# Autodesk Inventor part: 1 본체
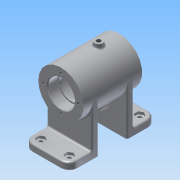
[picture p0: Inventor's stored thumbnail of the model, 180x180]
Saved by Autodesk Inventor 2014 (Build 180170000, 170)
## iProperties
Created: 2017-02
Part Number: 1 본체
Material: 알루미늄 6061
Document SubType Name: Modeling
Designer: 601-
Density: 2.71 g/cm^3
Appearance: 알루미늄 - 평지
Mass: 354.752 g
Surface Area: 426.244 cm^2
Volume: 130.905 cm^3
Author: 601-
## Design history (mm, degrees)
sketch "스케치1"
  geometry: L1 (-27, 52)-(27, 52); L2 (27, 52)-(27, -52); L3 (27, -52)-(-27, -52); L4 (-27, -52)-(-27, 52); L5 (-27, 52)-(27, -52); L6 (27, 52)-(-27, -52); L7 (-27, 17)-(27, 17); L8 (27, 17)-(27, -17); L9 (27, -17)-(-27, -17); L10 (-27, -17)-(-27, 17); L11 (-27, 17)-(27, -17); L12 (27, 17)-(-27, -17); 1 further point
  constraints: 24 end point, 4 midpoint, 4 parallel, 2 horizontal, 2 perpendicular, 1 point on line
  dimensions: "d0" = 54 distance of L1.start L1.end; "d1" = 104 distance of L1.end L2.end; "d2" = 17 distance from line of point (0, 0) L7
extrude "돌출1" new body sketch "스케치1" distance "d3" = 8; taper "d4" = 0 deg
sketch "스케치2"
  geometry: L1 (27, 0)-(-27, 0) reference; C1 r 27 at (0, 60); 1 further point
  constraints: 1 centre point, 1 vertical alignment
  dimensions: "d5" = 60 distance from line of C1.centre L1; "d6" = 54 diameter of C1
extrude "돌출2" join sketch "스케치2" stored distance "d7" = 70; taper "d8" = 0 deg
sketch "스케치3"
  geometry: L1 (27, -52)-(27, -17) reference; L2 (-27, -17)-(27, -17); L3 (27, -17)-(27, -25); L4 (27, -25)-(-27, -25); L5 (-27, -25)-(-27, -17); 1 further point
  constraints: 8 end point, 2 parallel, 1 horizontal, 1 perpendicular, 1 point on line
  dimensions: "d9" = 8 distance between parallel lines of L4 L2
extrude "돌출3" join sketch "스케치3" stored distance "d10" = 70; taper "d11" = 0 deg
node "작업 평면1"
node "작업 평면7"
sketch "스케치6"
  geometry: L1 (-35, 87)-(-35, 33) reference; L2 (-35, 87)-(35, 87) reference; L3 (-35, 60)-(-23, 60); L4 (-23, 60)-(-23, 76); L5 (-23, 76)-(-35, 76); L6 (-35, 76)-(-35, 60); L7 (-23, 60)-(-20, 60); L8 (-20, 60)-(-20, 74); L9 (-20, 74)-(-23, 74); L10 (-23, 74)-(-23, 60); L11 (-20, 60)-(20, 60); L12 (20, 60)-(20, 82); L13 (20, 82)-(-20, 82); L14 (-20, 82)-(-20, 60); L15 (20, 60)-(23, 60); L16 (23, 60)-(23, 74); L17 (23, 74)-(20, 74); L18 (20, 74)-(20, 60); L19 (23, 60)-(35, 60); L20 (35, 60)-(35, 76); L21 (35, 76)-(23, 76); L22 (23, 76)-(23, 60); 1 further point
  constraints: 40 end point, 10 parallel, 5 horizontal, 5 perpendicular, 1 midpoint
  dimensions: "d27" = 28 diameter of L17 L15; "d29" = 12 distance between parallel lines of L10 L6; "d31" = 3 distance between parallel lines of L8 L10; "d33" = 16 distance between parallel lines of L3 L5; "d34" = 14 distance between parallel lines of L7 L9; "d35" = 22 distance between parallel lines of L11 L13; "d36" = 40 distance between parallel lines of L18 L14; "d37" = 12 distance between parallel lines of L20 L16; "d38" = 16 distance between parallel lines of L19 L21; "d39" = 3 distance between parallel lines of L16 L12
revolve "회전1" sketch "스케치6" stored, may be unused: angle "d40" = 90 deg
sketch "스케치7" dims "d41" = 42
  geometry: C1 r 27 at (0, 0) reference; 3 further points
  constraints: 2 vertical alignment, 1 coincident, 2 other
hole "구멍2" sketch "스케치7" at (0, 21) diameter "d42" = 3.459; stored, may be unused: countersink angle "d46" = 90 deg, drill point angle "d48" = 118 deg; dims "d43" = 8, "d44" = 4, "d45" = 2, "d47" = 10
node "작업축1"
sketch "스케치8" dims "d52" = 42
  geometry: C1 r 16 at (0, 0) reference; C2 r 27 at (0, 0) reference; 3 further points
  constraints: 2 vertical alignment, 1 coincident, 2 other
hole "구멍3" sketch "스케치8" at (0, 21) diameter "d53" = 3.459; stored, may be unused: countersink angle "d57" = 90 deg, drill point angle "d59" = 118 deg; dims "d54" = 8, "d55" = 4, "d56" = 2, "d58" = 10
node "작업 평면2"
sketch "스케치9"
  geometry: L1 (0, 0)-(0, -27); L2 (0, 0)-(16.339, -25.16); 1 further point
  constraints: 4 end point, 1 vertical, 1 vertical alignment, 1 other
  dimensions: "d64" = 30 distance of L1.start L2.end; "d65" = 33 deg angle of L2 L1
node "작업 평면4"
node "작업 평면5"
sketch "스케치11"
  geometry: C1 r 6 at (0, 0); 1 further point
  constraints: 1 centre point
  dimensions: "d66" = 12 diameter of C1
extrude "돌출5" join sketch "스케치11" stored distance "d67" = 70; taper "d68" = 0 deg
sketch "스케치12"
  geometry: C1 r 6 at (0, 0) reference; 2 further points
  constraints: 1 coincident
hole "구멍4" sketch "스케치12" at (0, 0) diameter "d69" = 5.188; stored, may be unused: countersink angle "d73" = 90 deg, drill point angle "d75" = 118 deg; dims "d70" = 25, "d71" = 4, "d72" = 2, "d74" = 25
sketch "스케치13" dims "d78" = 9
  geometry: L1 (-12.5, -44.598)-(-17, -47.196); L2 (-17, -47.196)-(-21.5, -44.598); L3 (-21.5, -44.598)-(-21.5, -39.402); L4 (-21.5, -39.402)-(-17, -36.804); L5 (-17, -36.804)-(-12.5, -39.402); L6 (-12.5, -39.402)-(-12.5, -44.598); 4 further points
  constraints: 12 end point, 1 coincident, 1 horizontal alignment, 1 midpoint, 1 vertical alignment, 15 other
  dimensions: "d76" = 42 vertical distance of point (0, 0) point (-17, -42); "d77" = 17 horizontal distance of point (0, 0) point (-17, -42)
extrude "돌출6" cut sketch "스케치13" distance "d79" = 3; taper "d80" = 0 deg
hole "구멍5" sketch "스케치13" diameter "d81" = 5; stored, may be unused: countersink angle "d85" = 90 deg, drill point angle "d87" = 0 deg; dims "d82" = 25, "d83" = 4, "d84" = 2, "d86" = 25
fillet "모깎기1" dims "d88" = 2
fillet "모깎기2" dims "d89" = 2
fillet "모깎기3" dims "d90" = 2
fillet "모깎기4" dims "d91" = 2
fillet "모깎기5" dims "d92" = 0.3
fillet "모깎기6" dims "d93" = 2
chamfer "모따기1" distance "d94" = 1; stored, may be unused: second distance "d95" = 2, angle "d96" = 45 deg
chamfer "모따기2" distance "d97" = 1; stored, may be unused: second distance "d98" = 2, angle "d99" = 45 deg
node "작업 평면6"
sketch "스케치14"
  geometry: L1 (35, 33)-(35, 87) reference; L2 (35, 87)-(-35, 87) reference; L3 (-35, 87)-(-35, 33) reference; 2 further points
  constraints: 1 other
  dimensions: "d102" = 27 distance from line of point (0, 60) L2; "d103" = 35 distance from line of point (0, 60) L3
feature "엠보싱1" sketch "스케치14" dims "d104" = 0.5, "d105" = 0
node "작업 평면8"
sketch "스케치15"
  geometry: L1 (27, 35)-(-27, 35) reference; C1 r 5 at (0, 10); 1 further point
  constraints: 1 centre point, 1 vertical alignment
  dimensions: "d107" = 25 distance from line of C1.centre L1; "d108" = 10 diameter of C1
extrude "돌출7" join sketch "스케치15" stored distance "d109" = 10; taper "d110" = 0 deg
sketch "스케치16"
  geometry: C1 r 5 at (0, 0) reference; 2 further points
  constraints: 1 coincident
hole "구멍6" sketch "스케치16" at (0, 0) diameter "d111" = 5.188; stored, may be unused: countersink angle "d115" = 90 deg, drill point angle "d117" = 118 deg; dims "d112" = 20, "d113" = 4, "d114" = 2, "d116" = 20
fillet "모깎기8" dims "d118" = 2
fillet "모깎기9" dims "d119" = 10
fillet "모깎기10" dims "d120" = 2
fillet "모깎기11" dims "d121" = 2
node "솔리드1"
mirror "대칭1"
pattern_circular "원형 패턴1" dims angle "d50" = 360 deg
pattern_circular "원형 패턴2" dims angle "d61" = 360 deg
mirror "대칭2"
mirror "대칭3"
other parameters: "d12" = 92, "d63" = -35, "d101" = -35, "d106" = 92
